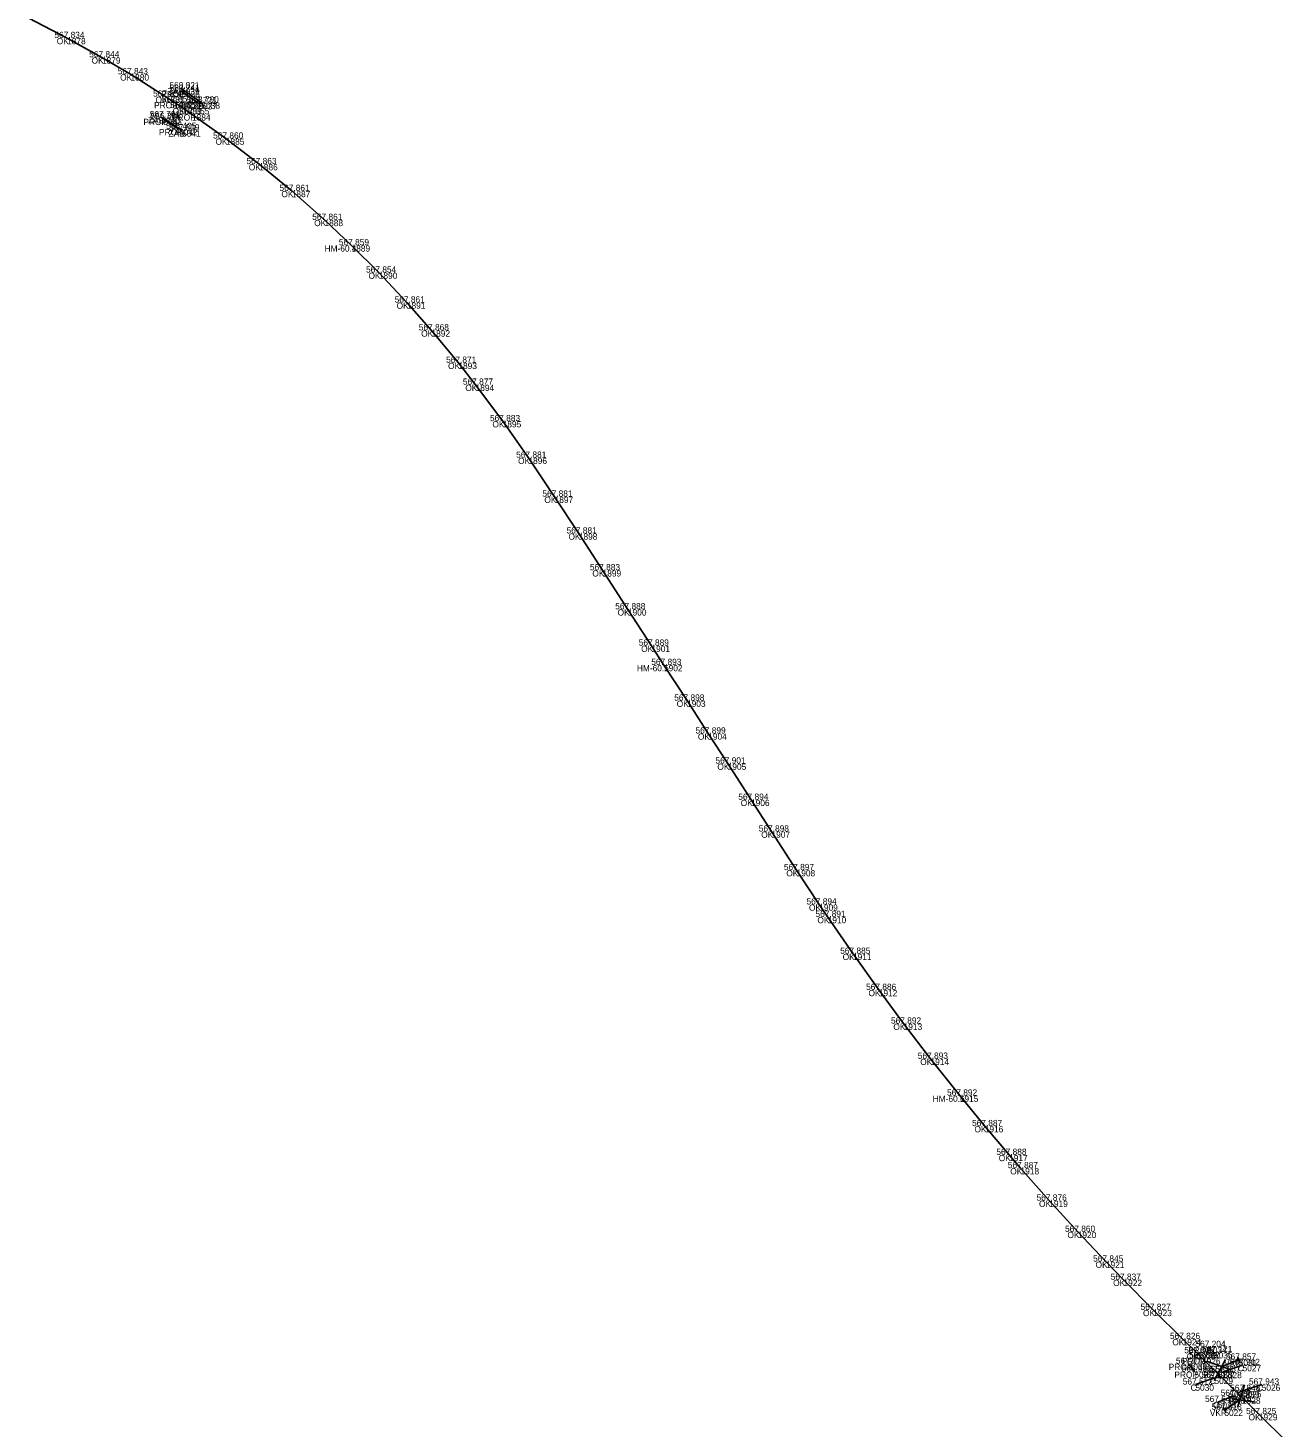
# Model space of a CAD drawing. Extents: x -631472 to -620808, y -1122356 to -1115125.
# Drawn here: x -622793.5 to -622551.4, y -1121233.6 to -1120964.2 of the extents above; entities that cross this region are included whole.
import ezdxf

# ---------------------------------------------------------------- set-up
doc = ezdxf.new("R2010")
doc.units = 0
for name, color, linetype in [('Vrstva 1', 7, 'Continuous'), ('Vrstva 17', 7, 'Continuous'), ('Vrstva 18', 7, 'Continuous'), ('Vrstva 4', 7, 'Continuous'), ('Vrstva 51', 7, 'Continuous'), ('Vrstva 60', 7, 'Continuous'), ('Vrstva 61', 7, 'Continuous'), ('Vrstva 62', 7, 'Continuous')]:
    doc.layers.add(name, color=color, linetype=linetype)

msp = doc.modelspace()

# ---------------------------------------------------------------- linework, layer by layer
at = {"layer": 'Vrstva 1'}
msp.add_lwpolyline([(-622793.53, -1120962.31), (-622786.01, -1120966.17), (-622779.31, -1120969.89), (-622773.82, -1120973.15), (-622767.03, -1120977.45), (-622765.45, -1120978.5), (-622763.72, -1120979.65), (-622761.99, -1120980.85), (-622755.48, -1120985.51), (-622749.08, -1120990.43), (-622742.81, -1120995.59), (-622736.51, -1121001.16), (-622731.3, -1121006.06), (-622726.07, -1121011.3), (-622720.66, -1121017.06), (-622715.93, -1121022.43), (-622710.76, -1121028.66), (-622707.45, -1121032.88), (-622702.24, -1121039.89), (-622697.29, -1121046.93), (-622692.25, -1121054.42), (-622687.6, -1121061.5), (-622683.02, -1121068.58), (-622678.15, -1121076.1), (-622673.63, -1121083.09), (-622671.22, -1121086.81), (-622666.79, -1121093.67), (-622662.71, -1121099.99), (-622658.97, -1121105.78), (-622654.48, -1121112.75), (-622650.54, -1121118.85), (-622645.71, -1121126.28), (-622641.35, -1121132.89), (-622639.74, -1121135.3), (-622634.87, -1121142.38), (-622629.91, -1121149.34), (-622625.13, -1121155.82), (-622619.96, -1121162.58), (-622614.34, -1121169.67), (-622609.53, -1121175.54), (-622604.85, -1121181.08), (-622602.65, -1121183.63), (-622597.12, -1121189.88), (-622591.65, -1121195.88), (-622586.23, -1121201.61), (-622582.85, -1121205.11), (-622577.12, -1121210.9), (-622571.47, -1121216.51), (-622568.7, -1121219.24), (-622567.75, -1121220.18), (-622565.02, -1121222.88), (-622560.06, -1121227.77), (-622556.81, -1121230.96), (-622551.41, -1121236.29)], dxfattribs=at)
at = {"layer": 'Vrstva 17'}
for p, q in [((-622764.09, -1120975.86), (-622760.18, -1120978.57)), ((-622767.51, -1120981.71), (-622764.5, -1120983.68))]:
    msp.add_line(p, q, dxfattribs=at)
at = {"layer": 'Vrstva 18'}
for p, q in [((-622764.06, -1120976.36), (-622760.75, -1120978.71)), ((-622767.85, -1120981.41), (-622763.9, -1120983.94)), ((-622566.57, -1121218.05), (-622565.46, -1121219.03)), ((-622570.32, -1121221.27), (-622569.22, -1121222.77))]:
    msp.add_line(p, q, dxfattribs=at)
at = {"layer": 'Vrstva 4'}
for p, q in [((-622562.5, -1121222.28), (-622566.86, -1121220.78)), ((-622565.39, -1121224.5), (-622563.24, -1121220.42)), ((-622560.69, -1121220.48), (-622563.94, -1121221.77)), ((-622560.5, -1121220.95), (-622560.87, -1121220.02)), ((-622565.02, -1121222.88), (-622560.06, -1121227.77)), ((-622559.58, -1121225.29), (-622560.93, -1121229.7)), ((-622563.45, -1121230.11), (-622560.49, -1121228.24)), ((-622562, -1121228.01), (-622557.44, -1121228.67)), ((-622563.72, -1121229.69), (-622563.18, -1121230.54))]:
    msp.add_line(p, q, dxfattribs=at)
at = {"layer": 'Vrstva 51'}
for p, q in [((-622569.02, -1121225.27), (-622565.36, -1121223.97)), ((-622563.68, -1121222.84), (-622559.95, -1121221.51)), ((-622556.27, -1121225.27), (-622559.88, -1121226.5)), ((-622564.72, -1121228.63), (-622561.7, -1121227.45))]:
    msp.add_line(p, q, dxfattribs=at)
at = {"layer": 'Vrstva 60'}
for p, q in [((-622786.01, -1120966.17), (-622786.01, -1120966.17)), ((-622779.31, -1120969.89), (-622779.31, -1120969.89)), ((-622773.82, -1120973.15), (-622773.82, -1120973.15)), ((-622767.03, -1120977.45), (-622767.03, -1120977.45)), ((-622765.45, -1120978.5), (-622765.45, -1120978.5)), ((-622763.72, -1120979.65), (-622763.72, -1120979.65)), ((-622761.99, -1120980.85), (-622761.99, -1120980.85)), ((-622755.48, -1120985.51), (-622755.48, -1120985.51)), ((-622749.08, -1120990.43), (-622749.08, -1120990.43)), ((-622742.81, -1120995.59), (-622742.81, -1120995.59)), ((-622736.51, -1121001.16), (-622736.51, -1121001.16)), ((-622731.3, -1121006.06), (-622731.3, -1121006.06)), ((-622726.07, -1121011.3), (-622726.07, -1121011.3)), ((-622720.66, -1121017.06), (-622720.66, -1121017.06)), ((-622715.93, -1121022.43), (-622715.93, -1121022.43)), ((-622710.76, -1121028.66), (-622710.76, -1121028.66)), ((-622707.45, -1121032.88), (-622707.45, -1121032.88)), ((-622702.24, -1121039.89), (-622702.24, -1121039.89)), ((-622697.29, -1121046.93), (-622697.29, -1121046.93)), ((-622692.25, -1121054.42), (-622692.25, -1121054.42)), ((-622687.6, -1121061.5), (-622687.6, -1121061.5)), ((-622683.02, -1121068.58), (-622683.02, -1121068.58)), ((-622678.15, -1121076.1), (-622678.15, -1121076.1)), ((-622673.63, -1121083.09), (-622673.63, -1121083.09)), ((-622671.22, -1121086.81), (-622671.22, -1121086.81)), ((-622666.79, -1121093.67), (-622666.79, -1121093.67)), ((-622662.71, -1121099.99), (-622662.71, -1121099.99)), ((-622658.97, -1121105.78), (-622658.97, -1121105.78)), ((-622654.48, -1121112.75), (-622654.48, -1121112.75)), ((-622650.54, -1121118.85), (-622650.54, -1121118.85)), ((-622645.71, -1121126.28), (-622645.71, -1121126.28)), ((-622641.35, -1121132.89), (-622641.35, -1121132.89)), ((-622639.74, -1121135.3), (-622639.74, -1121135.3)), ((-622634.87, -1121142.38), (-622634.87, -1121142.38)), ((-622629.91, -1121149.34), (-622629.91, -1121149.34)), ((-622625.13, -1121155.82), (-622625.13, -1121155.82)), ((-622619.96, -1121162.58), (-622619.96, -1121162.58)), ((-622614.34, -1121169.67), (-622614.34, -1121169.67)), ((-622609.53, -1121175.54), (-622609.53, -1121175.54)), ((-622604.85, -1121181.08), (-622604.85, -1121181.08)), ((-622602.65, -1121183.63), (-622602.65, -1121183.63)), ((-622597.12, -1121189.88), (-622597.12, -1121189.88)), ((-622591.65, -1121195.88), (-622591.65, -1121195.88)), ((-622586.23, -1121201.61), (-622586.23, -1121201.61)), ((-622582.85, -1121205.11), (-622582.85, -1121205.11)), ((-622577.12, -1121210.9), (-622577.12, -1121210.9)), ((-622571.47, -1121216.51), (-622571.47, -1121216.51)), ((-622568.7, -1121219.24), (-622568.7, -1121219.24)), ((-622567.75, -1121220.18), (-622567.75, -1121220.18)), ((-622565.02, -1121222.88), (-622565.02, -1121222.88)), ((-622560.06, -1121227.77), (-622560.06, -1121227.77)), ((-622556.81, -1121230.96), (-622556.81, -1121230.96))]:
    msp.add_line(p, q, dxfattribs=at)

# ---------------------------------------------------------------- texts
for s, p in [('1878', (-622786.01, -1120967.36)), ('1879', (-622779.31, -1120971.09)), ('1880', (-622773.82, -1120974.35)), ('5039', (-622764.09, -1120977.06)), ('5036', (-622764.06, -1120977.56)), ('1881', (-622767.03, -1120978.65)), ('1882', (-622765.45, -1120979.7)), ('5037', (-622760.75, -1120979.91)), ('5038', (-622760.18, -1120979.77)), ('5040', (-622767.85, -1120982.61)), ('5043', (-622767.51, -1120982.91)), ('1883', (-622763.72, -1120980.85)), ('1884', (-622761.99, -1120982.05)), ('5042', (-622764.5, -1120984.88)), ('5041', (-622763.9, -1120985.14)), ('1885', (-622755.48, -1120986.71)), ('1886', (-622749.08, -1120991.63)), ('1887', (-622742.81, -1120996.79)), ('1888', (-622736.51, -1121002.36)), ('1889', (-622731.3, -1121007.26)), ('1890', (-622726.07, -1121012.5)), ('1891', (-622720.66, -1121018.26)), ('1892', (-622715.93, -1121023.63)), ('1893', (-622710.76, -1121029.86)), ('1894', (-622707.45, -1121034.08)), ('1895', (-622702.24, -1121041.09)), ('1896', (-622697.29, -1121048.13)), ('1897', (-622692.25, -1121055.62)), ('1898', (-622687.6, -1121062.7)), ('1899', (-622683.02, -1121069.78)), ('1900', (-622678.15, -1121077.3)), ('1901', (-622673.63, -1121084.29)), ('1902', (-622671.22, -1121088.01)), ('1903', (-622666.79, -1121094.87)), ('1904', (-622662.71, -1121101.19)), ('1905', (-622658.97, -1121106.98)), ('1906', (-622654.48, -1121113.95)), ('1907', (-622650.54, -1121120.05)), ('1908', (-622645.71, -1121127.48)), ('1909', (-622641.35, -1121134.09)), ('1910', (-622639.74, -1121136.5)), ('1911', (-622634.87, -1121143.58)), ('1912', (-622629.91, -1121150.54)), ('1913', (-622625.13, -1121157.02)), ('1914', (-622619.96, -1121163.78)), ('1915', (-622614.34, -1121170.87)), ('1916', (-622609.53, -1121176.74)), ('1917', (-622604.85, -1121182.28)), ('1918', (-622602.65, -1121184.83)), ('1919', (-622597.12, -1121191.08)), ('1920', (-622591.65, -1121197.08)), ('1921', (-622586.23, -1121202.81)), ('1922', (-622582.85, -1121206.31)), ('1923', (-622577.12, -1121212.1)), ('1924', (-622571.47, -1121217.71)), ('5034', (-622566.57, -1121219.25)), ('5033', (-622570.32, -1121222.47)), ('1925', (-622568.7, -1121220.44)), ('1926', (-622567.75, -1121221.38)), ('5035', (-622565.46, -1121220.23)), ('5031', (-622560.69, -1121221.68)), ('5027', (-622559.95, -1121222.71)), ('5032', (-622569.22, -1121223.97)), ('5029', (-622565.36, -1121225.17)), ('1927', (-622565.02, -1121224.08)), ('5028', (-622563.68, -1121224.04)), ('5030', (-622569.02, -1121226.47)), ('5025', (-622559.88, -1121227.7)), ('5026', (-622556.27, -1121226.47)), ('5023', (-622564.72, -1121229.83)), ('5024', (-622561.7, -1121228.65)), ('1928', (-622560.06, -1121228.97)), ('5022', (-622563.45, -1121231.31)), ('1929', (-622556.81, -1121232.16))]:
    msp.add_text(s, height=1.2, dxfattribs=at).set_placement(p)
at = {"layer": 'Vrstva 61'}
for s, p in [('567.834', (-622788.46, -1120966.17)), ('567.844', (-622781.76, -1120969.89)), ('567.843', (-622776.27, -1120973.15)), ('567.850', (-622769.48, -1120977.45)), ('568.821', (-622766.34, -1120975.86)), ('567.741', (-622766.31, -1120976.36)), ('567.851', (-622767.8, -1120978.5)), ('567.853', (-622766.18, -1120979.65)), ('567.721', (-622763.01, -1120978.71)), ('568.790', (-622762.63, -1120978.57)), ('567.761', (-622770.1, -1120981.41)), ('566.355', (-622769.96, -1120981.71)), ('567.855', (-622764.45, -1120980.85)), ('566.405', (-622766.96, -1120983.68)), ('567.809', (-622766.35, -1120983.94)), ('567.860', (-622757.93, -1120985.51)), ('567.863', (-622751.53, -1120990.43)), ('567.861', (-622745.17, -1120995.59)), ('567.861', (-622738.87, -1121001.16)), ('567.859', (-622733.75, -1121006.06)), ('567.854', (-622728.52, -1121011.3)), ('567.861', (-622723.02, -1121017.06)), ('567.868', (-622718.38, -1121022.43)), ('567.871', (-622713.12, -1121028.66)), ('567.877', (-622709.9, -1121032.88)), ('567.883', (-622704.69, -1121039.89)), ('567.881', (-622699.65, -1121046.93)), ('567.881', (-622694.61, -1121054.42)), ('567.881', (-622689.96, -1121061.5)), ('567.883', (-622685.47, -1121068.58)), ('567.888', (-622680.6, -1121076.1)), ('567.889', (-622676.08, -1121083.09)), ('567.893', (-622673.67, -1121086.81)), ('567.898', (-622669.25, -1121093.67)), ('567.899', (-622665.16, -1121099.99)), ('567.901', (-622661.33, -1121105.78)), ('567.894', (-622656.93, -1121112.75)), ('567.898', (-622652.99, -1121118.85)), ('567.897', (-622648.16, -1121126.28)), ('567.894', (-622643.81, -1121132.89)), ('567.891', (-622642.09, -1121135.3)), ('567.885', (-622637.33, -1121142.38)), ('567.886', (-622632.36, -1121149.34)), ('567.892', (-622627.57, -1121155.82)), ('567.893', (-622622.41, -1121162.58)), ('567.892', (-622616.79, -1121169.67)), ('567.887', (-622611.98, -1121175.54)), ('567.888', (-622607.3, -1121181.08)), ('567.887', (-622605.1, -1121183.63)), ('567.876', (-622599.57, -1121189.88)), ('567.860', (-622594.1, -1121195.88)), ('567.845', (-622588.69, -1121201.61)), ('567.837', (-622585.31, -1121205.11)), ('567.827', (-622579.57, -1121210.9)), ('567.826', (-622573.92, -1121216.51)), ('567.825', (-622571.16, -1121219.24)), ('567.204', (-622569.02, -1121218.05)), ('567.121', (-622567.72, -1121219.03)), ('567.073', (-622572.77, -1121221.27)), ('567.822', (-622570.2, -1121220.18)), ('567.857', (-622563.14, -1121220.48)), ('567.912', (-622562.4, -1121221.51)), ('566.956', (-622571.67, -1121222.77)), ('567.512', (-622571.46, -1121225.27)), ('567.823', (-622567.81, -1121223.97)), ('567.831', (-622567.37, -1121222.88)), ('567.837', (-622566.13, -1121222.84)), ('567.943', (-622558.72, -1121225.27)), ('567.829', (-622564.16, -1121227.45)), ('567.839', (-622562.51, -1121227.77)), ('567.848', (-622562.34, -1121226.5)), ('567.647', (-622567.17, -1121228.63)), ('567.813', (-622565.9, -1121230.11)), ('567.825', (-622559.27, -1121230.96))]:
    msp.add_text(s, height=1.2, dxfattribs=at).set_placement(p)
at = {"layer": 'Vrstva 62'}
for s, p in [('OK', (-622788, -1120967.36)), ('OK', (-622781.3, -1120971.09)), ('OK', (-622775.81, -1120974.35)), ('PROP', (-622767.89, -1120977.56)), ('ZAB', (-622766.69, -1120977.06)), ('PROP', (-622769.28, -1120979.7)), ('OK', (-622769.01, -1120978.65)), ('PROP', (-622764.59, -1120979.91)), ('ZAB', (-622762.78, -1120979.77)), ('PROP', (-622771.34, -1120982.91)), ('ZAB', (-622770.45, -1120982.61)), ('PROP', (-622765.82, -1120982.05)), ('OK', (-622765.71, -1120980.85)), ('PROP', (-622768.34, -1120984.88)), ('ZAB', (-622766.5, -1120985.14)), ('OK', (-622757.47, -1120986.71)), ('OK', (-622751.07, -1120991.63)), ('OK', (-622744.8, -1120996.79)), ('OK', (-622738.49, -1121002.36)), ('HM-60.4', (-622736.5, -1121007.26)), ('OK', (-622728.05, -1121012.5)), ('OK', (-622722.64, -1121018.26)), ('OK', (-622717.91, -1121023.63)), ('OK', (-622712.75, -1121029.86)), ('OK', (-622709.43, -1121034.08)), ('OK', (-622704.22, -1121041.09)), ('OK', (-622699.28, -1121048.13)), ('OK', (-622694.23, -1121055.62)), ('OK', (-622689.59, -1121062.7)), ('OK', (-622685, -1121069.78)), ('OK', (-622680.14, -1121077.3)), ('OK', (-622675.61, -1121084.29)), ('HM-60.5', (-622676.44, -1121088.01)), ('OK', (-622668.78, -1121094.87)), ('OK', (-622664.7, -1121101.19)), ('OK', (-622660.96, -1121106.98)), ('OK', (-622656.46, -1121113.95)), ('OK', (-622652.52, -1121120.05)), ('OK', (-622647.7, -1121127.48)), ('OK', (-622643.34, -1121134.09)), ('OK', (-622641.72, -1121136.5)), ('OK', (-622636.86, -1121143.58)), ('OK', (-622631.89, -1121150.54)), ('OK', (-622627.11, -1121157.02)), ('OK', (-622621.94, -1121163.78)), ('HM-60.6', (-622619.55, -1121170.87)), ('OK', (-622611.51, -1121176.74)), ('OK', (-622606.84, -1121182.28)), ('OK', (-622604.63, -1121184.83)), ('OK', (-622599.1, -1121191.08)), ('OK', (-622593.63, -1121197.08)), ('OK', (-622588.22, -1121202.81)), ('OK', (-622584.84, -1121206.31)), ('OK', (-622579.1, -1121212.1)), ('OK', (-622573.46, -1121217.71)), ('PROP', (-622570.4, -1121219.25)), ('PROP', (-622574.15, -1121222.47)), ('PROP', (-622571.59, -1121221.38)), ('OK', (-622570.69, -1121220.44)), ('PROP', (-622569.3, -1121220.23)), ('VKR', (-622563.49, -1121221.68)), ('C', (-622560.89, -1121222.71)), ('PROP', (-622573.06, -1121223.97)), ('PRJ', (-622567.5, -1121224.08)), ('C', (-622566.3, -1121225.17)), ('C', (-622564.62, -1121224.04)), ('C', (-622569.95, -1121226.47)), ('C', (-622560.82, -1121227.7)), ('C', (-622557.2, -1121226.47)), ('C', (-622565.65, -1121229.83)), ('C', (-622562.64, -1121228.65)), ('PRJ', (-622562.55, -1121228.97)), ('VKR', (-622566.25, -1121231.31)), ('OK', (-622558.8, -1121232.16))]:
    msp.add_text(s, height=1.2, dxfattribs=at).set_placement(p)

doc.saveas('drawing.dxf')
